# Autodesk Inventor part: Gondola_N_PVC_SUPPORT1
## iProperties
Shininess: 64.0
Length Units: 11272
Angle Units: 11279
Time Units: 11290
Mass Units: 11286
Length Display Precision: 3
Angle Display Precision: 2
Compacted: True
Part Number: Gondola_N_PVC_SUPPORT1
Document SubType Name: Modeling
Created: 2004-12
Designer: John Blackburn
Material: PVC-Piping
Manufacturer: Standard
Standards Organization: Custom
Density: 0.0
Volumn: 0.0
Area: 0.0
PropertySet Name: Model Information
Control State: 0
Master: False
Checked Out: False
Author: John Blackburn
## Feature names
1. Extrusion1
2. Hole1
